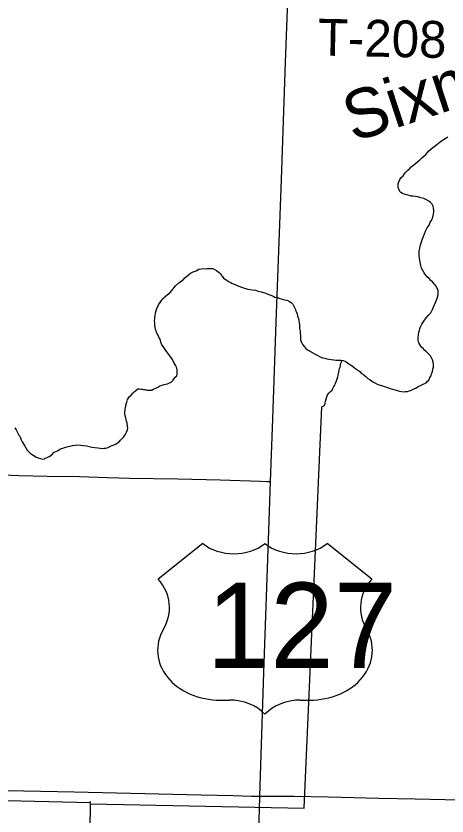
# Model space of a CAD drawing. Extents: x 0 to 64.8, y -5 to 22.
# Drawn here: x 4.744 to 5.41, y 15.77 to 17.005 of the extents above; entities that cross this region are included whole.
import ezdxf

# ---------------------------------------------------------------- set-up
doc = ezdxf.new("R2010")
doc.units = 0
for name, color, linetype in [('GM_X_County_Road', 7, 'Continuous'), ('GM_X_Minor_Lake_Text', 7, 'Continuous'), ('GM_X_Minor_River', 7, 'Continuous'), ('GM_X_State_Route', 7, 'Continuous'), ('GM_X_Township_Road', 7, 'Continuous'), ('GM_X_Township_Road_Text', 7, 'Continuous'), ('GM_X_US_Route', 7, 'Continuous'), ('GM_X_US_Shield', 7, 'Continuous')]:
    doc.layers.add(name, color=color, linetype=linetype)

msp = doc.modelspace()

# ---------------------------------------------------------------- linework, layer by layer
at = {"layer": 'GM_X_County_Road'}
msp.add_lwpolyline([(4.1309, 15.8224), (4.2374, 15.8201), (4.3338, 15.8181), (4.601, 15.8122), (4.8341, 15.8077), (5.0299, 15.8032), (5.0796, 15.8019), (5.1075, 15.8013), (5.1206, 15.8012)], dxfattribs=at)
at = {"layer": 'GM_X_Minor_River'}
for points in [[(5.339, 16.7558), (5.3417, 16.7584), (5.3437, 16.761), (5.346, 16.764), (5.3487, 16.7666), (5.3515, 16.7692), (5.3542, 16.7726), (5.3584, 16.7755), (5.3615, 16.7781), (5.3646, 16.7807), (5.3674, 16.7833), (5.3708, 16.7862), (5.3739, 16.7888), (5.3767, 16.7914), (5.3794, 16.7944), (5.3817, 16.797), (5.3848, 16.7996), (5.3876, 16.8022), (5.3918, 16.8051), (5.3941, 16.807), (5.3965, 16.8088), (5.3992, 16.811), (5.4026, 16.8136), (5.4069, 16.8162), (5.4107, 16.8188)], [(5.3775, 16.4392), (5.3794, 16.4415), (5.3813, 16.4433), (5.383, 16.4471), (5.3849, 16.4497), (5.3857, 16.4527), (5.387, 16.4565), (5.3878, 16.4603), (5.3886, 16.4633), (5.3887, 16.4656), (5.3888, 16.4682), (5.3884, 16.4709), (5.3874, 16.4743), (5.3859, 16.4774), (5.3841, 16.4805), (5.3804, 16.4844), (5.3778, 16.4871), (5.3755, 16.489), (5.3726, 16.4921), (5.3707, 16.4937), (5.3692, 16.4956), (5.3678, 16.498), (5.3667, 16.4999), (5.3656, 16.5022), (5.3652, 16.5045), (5.3649, 16.5083), (5.3654, 16.5124), (5.3663, 16.5174), (5.3671, 16.5204), (5.3675, 16.5223), (5.3688, 16.5257), (5.3708, 16.5298), (5.3739, 16.5343), (5.3774, 16.5391), (5.381, 16.5436), (5.3845, 16.5473), (5.3872, 16.5522), (5.3893, 16.5575), (5.3917, 16.5628), (5.3937, 16.568), (5.3953, 16.5726), (5.3957, 16.5756), (5.3962, 16.5779), (5.3958, 16.5801), (5.3952, 16.5836), (5.3941, 16.5855), (5.393, 16.5882), (5.3874, 16.5948), (5.3848, 16.5971), (5.3822, 16.5998), (5.3792, 16.6025), (5.3763, 16.6057), (5.3741, 16.6087), (5.3722, 16.6122), (5.3704, 16.616), (5.369, 16.6199), (5.368, 16.6252), (5.3673, 16.6309), (5.3667, 16.6366), (5.3668, 16.642), (5.3677, 16.6469), (5.3686, 16.6518), (5.3702, 16.6567), (5.3718, 16.6612), (5.3731, 16.665), (5.3747, 16.6688), (5.3763, 16.6729), (5.3791, 16.6785), (5.3818, 16.6826), (5.3838, 16.6868), (5.3854, 16.6898), (5.387, 16.6932), (5.3878, 16.6951), (5.3882, 16.6969), (5.3887, 16.6996), (5.3891, 16.703), (5.3892, 16.706), (5.3889, 16.7087), (5.3882, 16.7118), (5.3867, 16.7148), (5.3838, 16.7179), (5.3815, 16.7195), (5.3778, 16.7215), (5.3736, 16.7235), (5.3691, 16.7247), (5.3645, 16.726), (5.3608, 16.7264), (5.357, 16.7269), (5.3543, 16.7273), (5.3513, 16.7282), (5.3471, 16.7294), (5.3437, 16.7302), (5.3407, 16.7314), (5.3385, 16.733), (5.3366, 16.7342), (5.3341, 16.7407), (5.3341, 16.7434), (5.3342, 16.746), (5.335, 16.7494), (5.337, 16.7528), (5.339, 16.7558)], [(4.9145, 16.3631), (4.9161, 16.3664), (4.9166, 16.3691), (4.9163, 16.3721), (4.9156, 16.3767), (4.9149, 16.3798), (4.9142, 16.3821), (4.9135, 16.3851), (4.9128, 16.3882), (4.9122, 16.3927), (4.9127, 16.3984), (4.9136, 16.403), (4.9144, 16.4064), (4.9152, 16.4094), (4.9165, 16.4135), (4.9196, 16.418), (4.9223, 16.4206), (4.9243, 16.4229), (4.9266, 16.4251), (4.9289, 16.4273), (4.932, 16.4295), (4.9347, 16.4299), (4.937, 16.4294), (4.9392, 16.429), (4.9411, 16.4286), (4.9438, 16.4285), (4.946, 16.4277), (4.9537, 16.4279), (4.956, 16.4294), (4.9598, 16.4308), (4.9629, 16.4323), (4.966, 16.4345), (4.9698, 16.4355), (4.9729, 16.4366), (4.9752, 16.4369), (4.9778, 16.4376), (4.9801, 16.4383), (4.9836, 16.4398), (4.9863, 16.4424), (4.9879, 16.4446), (4.9898, 16.4476), (4.9922, 16.4498), (4.993, 16.4525), (4.9931, 16.4551), (4.9928, 16.4593), (4.9917, 16.4631), (4.9906, 16.4662), (4.9881, 16.4693), (4.9855, 16.4751), (4.9807, 16.4824), (4.9756, 16.489), (4.9719, 16.4944), (4.9693, 16.4978), (4.9679, 16.502), (4.9665, 16.5063), (4.9646, 16.5093), (4.9636, 16.5124), (4.9621, 16.5147), (4.961, 16.517), (4.9603, 16.5193), (4.9596, 16.5212), (4.9589, 16.5243), (4.9586, 16.5281), (4.9583, 16.5315), (4.958, 16.5349), (4.9594, 16.5471), (4.9614, 16.5539), (4.9639, 16.5595), (4.9666, 16.5632), (4.969, 16.5662), (4.9713, 16.5692), (4.974, 16.5718), (4.9775, 16.5748), (4.9814, 16.5777), (4.9849, 16.5814), (4.9904, 16.5885), (4.9954, 16.5934), (4.9997, 16.5963), (5.002, 16.5981), (5.0047, 16.6011), (5.0074, 16.603), (5.0109, 16.6063), (5.0136, 16.6081), (5.0175, 16.6103), (5.0221, 16.6121), (5.0263, 16.6143), (5.0301, 16.615), (5.0343, 16.6153), (5.0374, 16.6152), (5.0396, 16.6155), (5.0423, 16.6155), (5.0442, 16.6154), (5.0476, 16.6154), (5.0503, 16.6145), (5.0536, 16.6122), (5.0559, 16.6106), (5.0578, 16.6094), (5.06, 16.6071), (5.0614, 16.6048), (5.0629, 16.6029), (5.0644, 16.6005)], [(5.0644, 16.6005), (5.067, 16.599), (5.0696, 16.5974), (5.0723, 16.5954), (5.0749, 16.5942), (5.0772, 16.593), (5.0881, 16.5882), (5.0922, 16.5866), (5.0967, 16.585), (5.102, 16.5837), (5.1089, 16.5828), (5.1138, 16.5819), (5.1179, 16.5807), (5.1225, 16.5795), (5.1281, 16.5778), (5.133, 16.5758), (5.1376, 16.5742), (5.141, 16.573), (5.144, 16.5714), (5.1477, 16.5705), (5.1515, 16.5693), (5.1553, 16.5681), (5.1591, 16.5673), (5.1621, 16.5664), (5.1647, 16.5656), (5.1666, 16.5644), (5.1689, 16.5632), (5.1715, 16.5605), (5.1733, 16.5571), (5.174, 16.5551), (5.1751, 16.5532), (5.1758, 16.5513), (5.1769, 16.549), (5.178, 16.5455), (5.179, 16.5421), (5.1801, 16.5383), (5.1808, 16.5345), (5.1815, 16.5314), (5.1821, 16.528), (5.182, 16.5227), (5.1827, 16.5189), (5.183, 16.5154), (5.1833, 16.5116), (5.1832, 16.5086), (5.1835, 16.5055), (5.1842, 16.5025), (5.1853, 16.5006), (5.1868, 16.4979), (5.189, 16.4952), (5.1916, 16.4921), (5.1942, 16.4901), (5.2058, 16.4834), (5.21, 16.481), (5.2137, 16.4794), (5.2175, 16.4778), (5.2209, 16.477), (5.2239, 16.4761), (5.2269, 16.4753), (5.2307, 16.4748), (5.2349, 16.4744), (5.2379, 16.4739), (5.2414, 16.4742), (5.244, 16.4742), (5.2459, 16.4741), (5.2493, 16.4733), (5.2516, 16.4725), (5.2539, 16.4713), (5.2561, 16.4701), (5.258, 16.4685), (5.2606, 16.4669), (5.2632, 16.4654), (5.2662, 16.4626), (5.2688, 16.4607), (5.2718, 16.4587), (5.2748, 16.4564), (5.2778, 16.4536), (5.2812, 16.4513), (5.2841, 16.4486), (5.2875, 16.4458), (5.2912, 16.4435), (5.295, 16.4407), (5.2991, 16.4387), (5.3029, 16.4364), (5.3085, 16.4347), (5.3131, 16.4331), (5.3176, 16.4318), (5.3217, 16.4302), (5.3255, 16.429), (5.3293, 16.4282), (5.3327, 16.4273), (5.3361, 16.4261), (5.3395, 16.4257), (5.3425, 16.4252), (5.3452, 16.4255), (5.3486, 16.4258), (5.3513, 16.4265), (5.354, 16.4272), (5.3575, 16.429), (5.3613, 16.4309), (5.3651, 16.4331), (5.3775, 16.4392)], [(5.2165, 16.4019), (5.2208, 16.4044), (5.2221, 16.4108), (5.2253, 16.4206), (5.2273, 16.4232), (5.2296, 16.4255), (5.2323, 16.4277), (5.2332, 16.4303), (5.2347, 16.4333), (5.2363, 16.4356), (5.2371, 16.4375), (5.2379, 16.4397), (5.2391, 16.442), (5.24, 16.445), (5.2408, 16.4484), (5.2416, 16.4503), (5.2421, 16.4537), (5.2425, 16.4556), (5.2429, 16.4575), (5.2433, 16.4601), (5.2445, 16.4631), (5.245, 16.465), (5.245, 16.4669), (5.2458, 16.4692), (5.2477, 16.4737)], [(4.859, 15.7891), (5.1888, 15.7825), (5.2165, 16.4019)], [(4.7425, 16.3696), (4.7443, 16.3665), (4.7454, 16.3642), (4.7465, 16.3623), (4.7487, 16.3584), (4.7498, 16.3565), (4.7509, 16.3542), (4.7519, 16.3508), (4.7538, 16.3481), (4.7552, 16.3454), (4.7571, 16.3423), (4.7593, 16.3388), (4.7615, 16.335), (4.7637, 16.3323), (4.7659, 16.3303), (4.7682, 16.3288), (4.7708, 16.3272), (4.773, 16.3256), (4.7753, 16.3244), (4.7783, 16.3232), (4.7817, 16.322), (4.7836, 16.3216), (4.7874, 16.3211), (4.7893, 16.3226), (4.7924, 16.3236), (4.7955, 16.3255), (4.7993, 16.328), (4.8032, 16.3318), (4.8082, 16.3343), (4.8117, 16.3365), (4.8151, 16.3376), (4.8182, 16.3386), (4.8213, 16.3397), (4.8247, 16.3408), (4.8278, 16.3415), (4.8316, 16.3421), (4.8354, 16.3428), (4.8392, 16.3431), (4.8529, 16.3417), (4.857, 16.3408), (4.8612, 16.3396), (4.8657, 16.3391), (4.8703, 16.3386), (4.8741, 16.3381), (4.8775, 16.3377), (4.8801, 16.338), (4.8828, 16.3383), (4.8863, 16.3394), (4.8909, 16.3416), (4.8966, 16.3437), (4.9032, 16.3481), (4.9055, 16.3503), (4.9079, 16.353), (4.9102, 16.3552), (4.9126, 16.3589), (4.9145, 16.3631)], [(3.4389, 15.8253), (4.859, 15.7914)], [(4.8507, 15.0442), (4.859, 15.793)]]:
    msp.add_lwpolyline(points, dxfattribs=at)
at = {"layer": 'GM_X_State_Route'}
msp.add_lwpolyline([(5.1206, 15.8012), (5.1737, 15.8009), (5.2266, 15.7998), (5.3043, 15.7979), (5.3602, 15.7967), (5.5219, 15.7936)], dxfattribs=at)
at = {"layer": 'GM_X_Township_Road'}
msp.add_lwpolyline([(4.1326, 16.3146), (4.1377, 16.3144), (4.147, 16.314), (4.1811, 16.3133), (4.2153, 16.3122), (4.2711, 16.3105), (4.33, 16.3085), (4.4449, 16.3052), (4.5317, 16.3024), (4.5596, 16.3015), (4.5814, 16.3009), (4.6279, 16.2997), (4.662, 16.2989), (4.7117, 16.2974), (4.7489, 16.2962), (4.7923, 16.295), (4.842, 16.2942), (4.8855, 16.293), (4.9196, 16.2921), (4.9941, 16.2906), (5.0592, 16.2892), (5.1217, 16.2874), (5.1315, 16.2869), (5.1372, 16.2867)], dxfattribs=at)
at = {"layer": 'GM_X_US_Route'}
for points in [[(5.1206, 15.8012), (5.1266, 15.9917), (5.1356, 16.2403), (5.1372, 16.2867), (5.1406, 16.3833), (5.1459, 16.5324), (5.1541, 16.7531), (5.1604, 16.9333), (5.1644, 17.0434), (5.1669, 17.1135), (5.1736, 17.2933)], [(5.1189, 15.7512), (5.1199, 15.7798), (5.1206, 15.8012)]]:
    msp.add_lwpolyline(points, dxfattribs=at)
at = {"layer": 'GM_X_US_Shield'}
for p, q in [((5.0324, 16.191), (4.9638, 16.1361)), ((5.2934, 16.1361), (5.2247, 16.191)), ((5.0599, 15.9493), (5.0736, 15.9493)), ((5.1835, 15.9493), (5.1972, 15.9493))]:
    msp.add_line(p, q, dxfattribs=at)
for centre, major_axis, start_param, end_param in [((5.0805, 16.2302), (-0.0687, 0), 0.795399, 2.346194), ((5.1766, 16.2302), (-0.0687, 0), 0.795399, 2.346194), ((4.885, 16.092), (0.0961, 0), 5.838949, 6.894067), ((5.3721, 16.092), (-0.0961, 0), 5.672304, 6.727422), ((5.0588, 16.0262), (0.0961, 0), 2.702327, 4.723529), ((5.1983, 16.0262), (-0.0961, 0), 1.559657, 3.580859), ((5.0736, 15.8944), (-0.0687, 0), 3.785094, 4.712389), ((5.1835, 15.8944), (-0.0687, 0), 4.712389, 5.639684)]:
    msp.add_ellipse(centre, major_axis=major_axis, ratio=0.8, start_param=start_param, end_param=end_param, dxfattribs=at)

# ---------------------------------------------------------------- texts
at = {"layer": 'GM_X_Minor_Lake_Text'}
msp.add_text('Sixmile', height=0.07579, rotation=18.2, dxfattribs=at).set_placement((5.2645, 16.8101))
at = {"layer": 'GM_X_Township_Road_Text'}
msp.add_text('T-208', height=0.05682, rotation=358.8773, dxfattribs=at).set_placement((5.2098, 16.9442))
at = {"layer": 'GM_X_US_Shield'}
msp.add_text('127', height=0.13184, dxfattribs=at).set_placement((5.0385, 15.9988))

doc.saveas('drawing.dxf')
